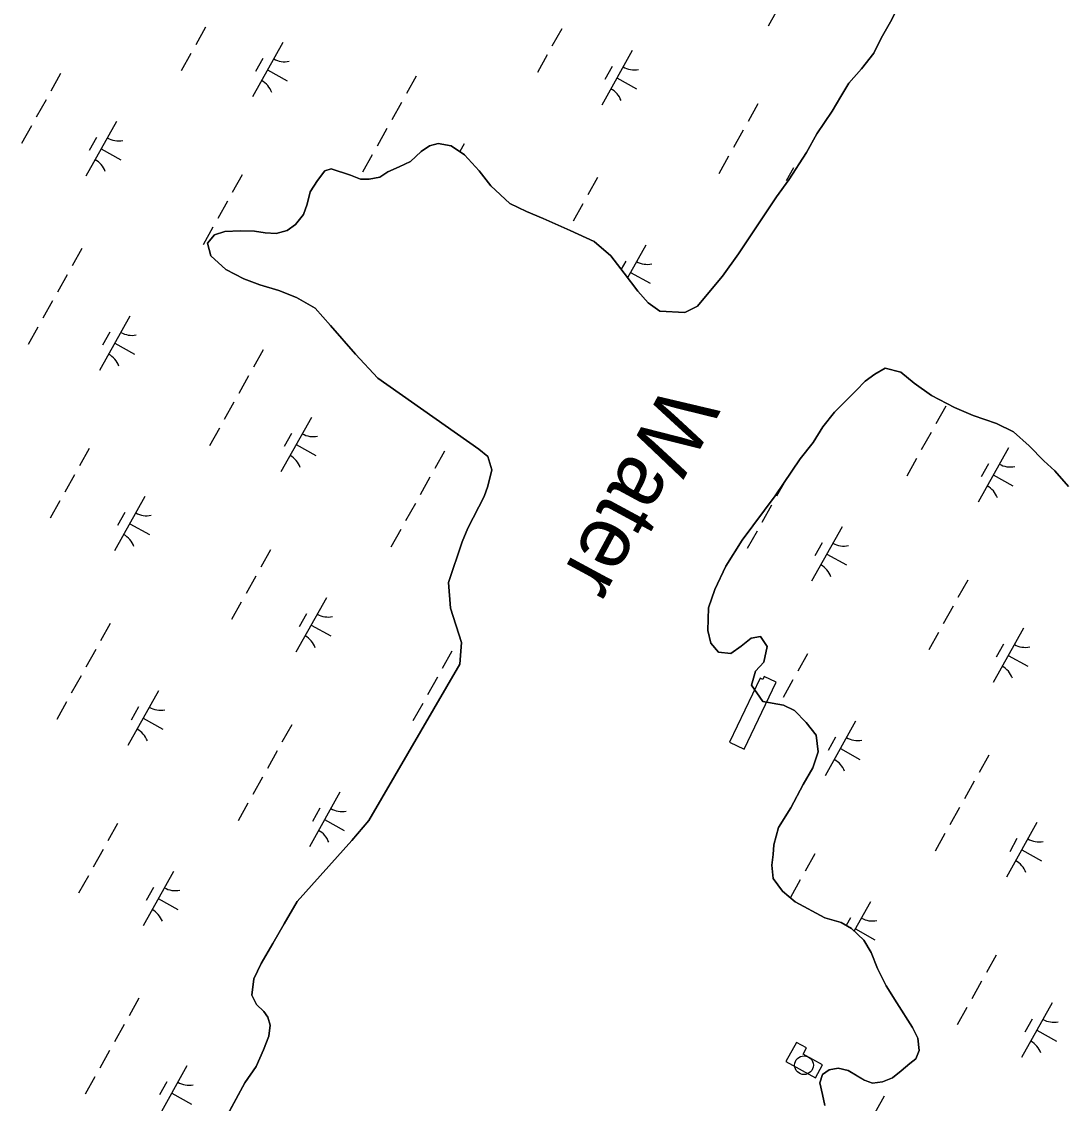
# Model space of a CAD drawing. Extents: x 3923531 to 3943530, y 207391 to 229799.
# Drawn here: x 3933394 to 3934228, y 219861 to 220728 of the extents above; entities that cross this region are included whole.
import ezdxf

# ---------------------------------------------------------------- set-up
doc = ezdxf.new("R2010")
doc.units = 0
for name, color, linetype in [('V-CHAN-DOCK', 7, 'Continuous'), ('V-DOMW-TANK', 7, 'Continuous'), ('V-RIVR-IDEN', 7, 'Continuous'), ('V-TOPO-SHOR', 7, 'Continuous'), ('V-WETL-SWMP', 7, 'Continuous')]:
    doc.layers.add(name, color=color, linetype=linetype)

msp = doc.modelspace()

# ---------------------------------------------------------------- linework, layer by layer
at = {"layer": 'V-CHAN-DOCK'}
for points in [[(3933984.89, 220201.83), (3933960.29, 220150.43), (3933971.99, 220144.83), (3933997.67, 220198.47), (3933988.17, 220203.02), (3933987.1, 220200.77)], [(3934034.88, 219892.13), (3934019.22, 219900.74), (3934021.97, 219905.73), (3934013.91, 219910.16), (3934005.47, 219894.8), (3934029.18, 219881.76)]]:
    msp.add_lwpolyline(points, close=True, dxfattribs=at)
at = {"layer": 'V-DOMW-TANK'}
msp.add_circle((3934019.97, 219891.86), 7.5, dxfattribs=at)
at = {"layer": 'V-TOPO-SHOR'}
for points in [[(3933542.45, 220550.23), (3933548.06, 220556.9), (3933556.4, 220559.39), (3933568.87, 220560.05), (3933580.14, 220559.73), (3933588.63, 220558.46), (3933597.53, 220557.77), (3933606.26, 220560.25), (3933612.83, 220564.93), (3933619.45, 220572.98), (3933622.3, 220581.46), (3933624.58, 220591.12), (3933630.41, 220600.36), (3933636.43, 220608.02), (3933641.59, 220609.74), (3933656.96, 220604.44), (3933664.85, 220601.39), (3933671.77, 220601.32), (3933680.49, 220603.01), (3933686.87, 220607.29), (3933696.01, 220611.16), (3933704.95, 220615.42), (3933713.54, 220623.44), (3933720.12, 220628.12), (3933727.06, 220629.83), (3933737.53, 220628.14), (3933748.14, 220620.9), (3933760.07, 220608.12), (3933769.25, 220596.15), (3933784.53, 220581.95), (3933797.92, 220575.48), (3933811.31, 220570), (3933832.78, 220560.28), (3933851.88, 220551.38), (3933865.41, 220539.96), (3933875.95, 220526.01), (3933886.88, 220511.65), (3933895.29, 220502.46), (3933904.52, 220495.64), (3933924.68, 220494.64), (3933934.83, 220499.68), (3933941.23, 220507.33), (3933954.66, 220523.81), (3933967.5, 220541.68), (3933998.05, 220587.26), (3934007.88, 220600.81), (3934021.96, 220622.82), (3934030.23, 220637.77), (3934042.48, 220655.84), (3934049.52, 220667.44), (3934055.77, 220678.26), (3934065.98, 220689.82), (3934076, 220702.38), (3934081.67, 220714.39), (3934089.12, 220727.37), (3934093.76, 220736.03)], [(3933550.1, 219836.96), (3933572.49, 219877.88), (3933581.52, 219890.84), (3933587.4, 219904.24), (3933591.67, 219915.07), (3933592.75, 219923.96), (3933590.83, 219930.32), (3933587.52, 219934.9), (3933581.64, 219940.5), (3933577.96, 219947.86), (3933579.68, 219960.9), (3933585.54, 219973.3), (3933594.81, 219989.43), (3933603.87, 220004.96), (3933614.15, 220023.05), (3933657.94, 220071.71), (3933671.64, 220087.9), (3933744.4, 220212.98), (3933745.85, 220230.32), (3933736.95, 220257.77), (3933735.38, 220278.46), (3933746.31, 220310.92), (3933750.78, 220321.95), (3933763.9, 220347.33), (3933766.96, 220355.61), (3933770.06, 220368.64), (3933766.81, 220379.36), (3933759.55, 220385.17), (3933678.88, 220441.89), (3933660.95, 220461.21), (3933640.88, 220484.12), (3933628.56, 220498.1), (3933613.81, 220506.56), (3933599.63, 220512.25), (3933584.44, 220516.76), (3933571.63, 220521.44), (3933557.07, 220529.11), (3933545.12, 220539.92), (3933542.45, 220550.23)], [(3933957.39, 220291.51), (3933970.46, 220312.34), (3933996.94, 220347.68), (3934016.83, 220377.35), (3934027.26, 220390.49), (3934035.1, 220403.07), (3934044.33, 220414.85), (3934061.72, 220432.27), (3934068.91, 220439.52), (3934076.69, 220445.17), (3934084.85, 220450.04), (3934097.48, 220446.94), (3934108.27, 220438.12), (3934122.01, 220428.09), (3934140.31, 220418.6), (3934155.48, 220412.11), (3934174.01, 220405.79), (3934187.79, 220398.92), (3934200.33, 220387.91), (3934212.08, 220375.72), (3934220.7, 220367.71), (3934231.65, 220355.34)], [(3934036.6, 219859.61), (3934034.71, 219868.53), (3934032.63, 219877.65), (3934034.68, 219884.36), (3934040.06, 219888.06), (3934047.2, 219889.37), (3934055.29, 219887.51), (3934068.27, 219879.86), (3934074.77, 219877.42), (3934082.69, 219878.52), (3934090.84, 219881.8), (3934097.62, 219887.46), (3934104.81, 219893.33), (3934109.59, 219897.04), (3934112.03, 219903.54), (3934111.15, 219913.44), (3934106.88, 219922.19), (3934094.23, 219941.9), (3934085.86, 219955.44), (3934078.88, 219969.36), (3934073.67, 219982.08), (3934067.84, 219992.03), (3934058.05, 220001.43), (3934049.59, 220006.27), (3934036.77, 220009.96), (3934012.77, 220022.67), (3934002.77, 220031.28), (3933995.16, 220041.45), (3933994.27, 220051.95), (3933995.16, 220060.64), (3933995.83, 220068.35), (3933999.53, 220082.16), (3934009.39, 220098.08), (3934019.28, 220116.58), (3934026.93, 220129.95), (3934031.22, 220142.77), (3934029.58, 220156.23), (3934021.77, 220166.4), (3934012.37, 220175.8), (3934003.52, 220180.04), (3933986.93, 220183.18), (3933977.96, 220196.14), (3933981.25, 220207.38), (3933987.85, 220214.63), (3933990.55, 220227.07), (3933985.09, 220235.23), (3933977.56, 220233.73), (3933969.78, 220227.28), (3933961.41, 220221.43), (3933951.53, 220222.72), (3933945.47, 220229.71), (3933943, 220240.02), (3933943.39, 220258.02), (3933948.69, 220272.8), (3933957.39, 220291.51)]]:
    msp.add_lwpolyline(points, dxfattribs=at)
at = {"layer": 'V-WETL-SWMP'}
for p, q in [((3934015.62, 220767.66), (3933991.23, 220724.01)), ((3934093.76, 220736.03), (3934089.12, 220727.37)), ((3934089.12, 220727.37), (3934081.66, 220714.39)), ((3933540.84, 220723.02), (3933533.04, 220709.05)), ((3933826.03, 220721.76), (3933818.23, 220707.8)), ((3933602.8, 220710.83), (3933578.41, 220667.18)), ((3934081.66, 220714.39), (3934076, 220702.38)), ((3933529.13, 220702.06), (3933521.33, 220688.09)), ((3933814.33, 220700.81), (3933806.53, 220686.84)), ((3933882.42, 220704.35), (3933858.03, 220660.7)), ((3934076, 220702.38), (3934065.98, 220689.82)), ((3933586.8, 220698), (3933580.94, 220687.53)), ((3933866.42, 220691.53), (3933860.56, 220681.05)), ((3933424.92, 220685.88), (3933417.12, 220671.91)), ((3933590.61, 220689), (3933606.32, 220680.22)), ((3933709.46, 220683.8), (3933701.66, 220669.83)), ((3933870.23, 220682.52), (3933885.94, 220673.75)), ((3934065.98, 220689.82), (3934055.77, 220678.26)), ((3934055.77, 220678.26), (3934049.52, 220667.44)), ((3933413.21, 220664.93), (3933405.41, 220650.96)), ((3934049.52, 220667.44), (3934042.48, 220655.84)), ((3933697.76, 220662.84), (3933689.95, 220648.87)), ((3933982.95, 220661.59), (3933975.15, 220647.62)), ((3934042.48, 220655.84), (3934030.22, 220637.77)), ((3933469.6, 220647.51), (3933445.21, 220603.86)), ((3933401.51, 220643.98), (3933393.71, 220630.01)), ((3933686.05, 220641.89), (3933678.25, 220627.92)), ((3933971.25, 220640.64), (3933963.44, 220626.67)), ((3933453.6, 220634.69), (3933447.74, 220624.21)), ((3933727.06, 220629.83), (3933720.12, 220628.12)), ((3933737.53, 220628.14), (3933727.06, 220629.83)), ((3933748.01, 220629.7), (3933744.49, 220623.39)), ((3934030.22, 220637.77), (3934021.96, 220622.82)), ((3933457.41, 220625.69), (3933473.12, 220616.91)), ((3933674.35, 220620.94), (3933666.54, 220606.97)), ((3933713.54, 220623.44), (3933704.95, 220615.42)), ((3933720.12, 220628.12), (3933713.54, 220623.44)), ((3933748.14, 220620.9), (3933737.53, 220628.14)), ((3934021.96, 220622.82), (3934007.88, 220600.81)), ((3933704.95, 220615.42), (3933696.01, 220611.16)), ((3933760.07, 220608.12), (3933748.14, 220620.9)), ((3933959.54, 220619.69), (3933951.74, 220605.72)), ((3933570.13, 220604.76), (3933562.33, 220590.79)), ((3933636.43, 220608.01), (3933630.41, 220600.36)), ((3933641.59, 220609.74), (3933636.43, 220608.01)), ((3933656.96, 220604.44), (3933641.59, 220609.74)), ((3933664.85, 220601.39), (3933656.96, 220604.44)), ((3933686.87, 220607.29), (3933680.49, 220603.01)), ((3933696.01, 220611.16), (3933686.87, 220607.29)), ((3933769.25, 220596.15), (3933760.07, 220608.12)), ((3934011.63, 220610.4), (3934005.78, 220599.93)), ((3933630.41, 220600.36), (3933624.58, 220591.12)), ((3933671.77, 220601.32), (3933664.85, 220601.39)), ((3933680.49, 220603.01), (3933671.77, 220601.32)), ((3933784.53, 220581.95), (3933769.25, 220596.15)), ((3933854.68, 220602.67), (3933846.87, 220588.7)), ((3934007.88, 220600.81), (3933998.05, 220587.26)), ((3933624.58, 220591.12), (3933622.3, 220581.45)), ((3933998.05, 220587.26), (3933967.51, 220541.68)), ((3933558.43, 220583.8), (3933550.63, 220569.84)), ((3933622.3, 220581.45), (3933619.45, 220572.98)), ((3933797.92, 220575.48), (3933784.53, 220581.95)), ((3933842.97, 220581.72), (3933835.17, 220567.75)), ((3933619.45, 220572.98), (3933612.83, 220564.93)), ((3933811.31, 220570), (3933797.92, 220575.48)), ((3933832.78, 220560.28), (3933811.31, 220570)), ((3933546.72, 220562.85), (3933538.92, 220548.88)), ((3933612.83, 220564.93), (3933606.26, 220560.25)), ((3933548.06, 220556.9), (3933542.45, 220550.23)), ((3933556.39, 220559.38), (3933548.06, 220556.9)), ((3933568.86, 220560.05), (3933556.39, 220559.38)), ((3933580.14, 220559.73), (3933568.86, 220560.05)), ((3933588.63, 220558.46), (3933580.14, 220559.73)), ((3933597.53, 220557.77), (3933588.63, 220558.46)), ((3933606.26, 220560.25), (3933597.53, 220557.77)), ((3933851.87, 220551.38), (3933832.78, 220560.28)), ((3933441.86, 220545.84), (3933434.05, 220531.87)), ((3933542.45, 220550.23), (3933545.11, 220539.92)), ((3933865.41, 220539.96), (3933851.87, 220551.38)), ((3933893.23, 220548.58), (3933878.64, 220522.47)), ((3933545.11, 220539.92), (3933557.07, 220529.11)), ((3933875.94, 220526.01), (3933865.41, 220539.96)), ((3933877.22, 220535.75), (3933873.55, 220529.18)), ((3933967.51, 220541.68), (3933954.66, 220523.81)), ((3933557.07, 220529.11), (3933571.63, 220521.44)), ((3933886.87, 220511.65), (3933875.94, 220526.01)), ((3933881.03, 220526.75), (3933896.75, 220517.97)), ((3933430.15, 220524.88), (3933422.35, 220510.91)), ((3933571.63, 220521.44), (3933584.44, 220516.76)), ((3933954.66, 220523.81), (3933941.23, 220507.33)), ((3933584.44, 220516.76), (3933599.63, 220512.25)), ((3933599.63, 220512.25), (3933613.81, 220506.56)), ((3933895.29, 220502.46), (3933886.87, 220511.65)), ((3933418.45, 220503.93), (3933410.64, 220489.96)), ((3933613.81, 220506.56), (3933628.56, 220498.1)), ((3933904.51, 220495.64), (3933895.29, 220502.46)), ((3933934.82, 220499.68), (3933924.68, 220494.64)), ((3933941.23, 220507.33), (3933934.82, 220499.68)), ((3933480.41, 220491.74), (3933456.02, 220448.09)), ((3933628.56, 220498.1), (3933640.88, 220484.12)), ((3933924.68, 220494.64), (3933904.51, 220495.64)), ((3933406.74, 220482.98), (3933398.94, 220469.01)), ((3933640.88, 220484.12), (3933660.95, 220461.21)), ((3933464.4, 220478.92), (3933458.55, 220468.44)), ((3933468.21, 220469.92), (3933483.93, 220461.14)), ((3933587.07, 220464.71), (3933579.27, 220450.74)), ((3933660.95, 220461.21), (3933678.88, 220441.89)), ((3934084.85, 220450.04), (3934076.69, 220445.17)), ((3934097.48, 220446.94), (3934084.85, 220450.04)), ((3933575.37, 220443.76), (3933567.56, 220429.79)), ((3933678.88, 220441.89), (3933759.55, 220385.17)), ((3934068.91, 220439.52), (3934061.72, 220432.27)), ((3934076.69, 220445.17), (3934068.91, 220439.52)), ((3934108.27, 220438.12), (3934097.48, 220446.94)), ((3934061.72, 220432.27), (3934044.33, 220414.85)), ((3934122.01, 220428.09), (3934108.27, 220438.12)), ((3933563.66, 220422.81), (3933555.86, 220408.84)), ((3934140.31, 220418.6), (3934122.01, 220428.09)), ((3934044.33, 220414.85), (3934035.1, 220403.07)), ((3934133.4, 220419.47), (3934125.6, 220405.5)), ((3934155.48, 220412.11), (3934140.31, 220418.6)), ((3933625.62, 220410.62), (3933601.23, 220366.97)), ((3934174.01, 220405.79), (3934155.48, 220412.11)), ((3934187.79, 220398.92), (3934174.01, 220405.79)), ((3933551.96, 220401.85), (3933544.15, 220387.89)), ((3933609.62, 220397.79), (3933603.77, 220387.32)), ((3934035.1, 220403.07), (3934027.26, 220390.49)), ((3934121.69, 220398.52), (3934113.89, 220384.55)), ((3934200.33, 220387.91), (3934187.79, 220398.92)), ((3933613.43, 220388.79), (3933629.14, 220380.01)), ((3934027.26, 220390.49), (3934016.83, 220377.34)), ((3934212.08, 220375.72), (3934200.33, 220387.91)), ((3933447.74, 220385.67), (3933439.94, 220371.7)), ((3933732.28, 220383.59), (3933724.48, 220369.62)), ((3933759.55, 220385.17), (3933766.81, 220379.35)), ((3933766.81, 220379.35), (3933770.06, 220368.64)), ((3934183.65, 220386.33), (3934159.27, 220342.68)), ((3934016.83, 220377.34), (3933996.94, 220347.68)), ((3934109.99, 220377.57), (3934102.19, 220363.6)), ((3934167.65, 220373.51), (3934161.8, 220363.03)), ((3934220.7, 220367.72), (3934212.08, 220375.72)), ((3933436.04, 220364.72), (3933428.23, 220350.75)), ((3933720.58, 220362.63), (3933712.78, 220348.67)), ((3933770.06, 220368.64), (3933766.96, 220355.61)), ((3934171.46, 220364.51), (3934187.18, 220355.73)), ((3934231.65, 220355.34), (3934220.7, 220367.72)), ((3933766.96, 220355.61), (3933763.9, 220347.34)), ((3934003.99, 220358.19), (3933997.97, 220347.42)), ((3933424.33, 220343.77), (3933416.53, 220329.8)), ((3933492.42, 220347.31), (3933468.03, 220303.65)), ((3933763.9, 220347.34), (3933750.78, 220321.95)), ((3933996.94, 220347.68), (3933970.46, 220312.34)), ((3933708.87, 220341.68), (3933701.07, 220327.71)), ((3933994.07, 220340.43), (3933986.27, 220326.46)), ((3933476.42, 220334.48), (3933470.56, 220324)), ((3933480.23, 220325.48), (3933495.94, 220316.7)), ((3933697.17, 220320.73), (3933689.37, 220306.76)), ((3933750.78, 220321.95), (3933746.31, 220310.92)), ((3933982.37, 220319.48), (3933974.56, 220305.51)), ((3934050.45, 220323.02), (3934026.07, 220279.37)), ((3933746.31, 220310.92), (3933735.38, 220278.46)), ((3933970.46, 220312.34), (3933957.39, 220291.51)), ((3934034.45, 220310.19), (3934028.6, 220299.72)), ((3933592.95, 220304.55), (3933585.15, 220290.58)), ((3934038.26, 220301.19), (3934053.97, 220292.41)), ((3933581.25, 220283.59), (3933573.45, 220269.63)), ((3933957.39, 220291.51), (3933948.69, 220272.8)), ((3933735.38, 220278.46), (3933736.95, 220257.77)), ((3934150.99, 220280.26), (3934143.19, 220266.29)), ((3933637.63, 220266.18), (3933613.25, 220222.53)), ((3933948.69, 220272.8), (3933943.39, 220258.02)), ((3933569.54, 220262.64), (3933561.74, 220248.67)), ((3933736.95, 220257.77), (3933745.85, 220230.32)), ((3933943.39, 220258.02), (3933943.01, 220240.02)), ((3934139.28, 220259.31), (3934131.48, 220245.34)), ((3933621.63, 220253.36), (3933615.78, 220242.88)), ((3933464.68, 220245.63), (3933456.87, 220231.66)), ((3933625.44, 220244.36), (3933641.15, 220235.58)), ((3933943.01, 220240.02), (3933945.47, 220229.71)), ((3934195.67, 220241.89), (3934171.28, 220198.24)), ((3933969.78, 220227.28), (3933977.56, 220233.73)), ((3933977.56, 220233.73), (3933985.09, 220235.23)), ((3933985.09, 220235.23), (3933990.55, 220227.07)), ((3934127.58, 220238.36), (3934119.78, 220224.39)), ((3933452.97, 220224.67), (3933445.17, 220210.71)), ((3933738.17, 220223.42), (3933730.36, 220209.45)), ((3933745.85, 220230.32), (3933744.4, 220212.98)), ((3933945.47, 220229.71), (3933951.53, 220222.72)), ((3933951.53, 220222.72), (3933961.41, 220221.43)), ((3933961.41, 220221.43), (3933969.78, 220227.28)), ((3933990.55, 220227.07), (3933987.85, 220214.63)), ((3934179.66, 220229.07), (3934173.81, 220218.59)), ((3933987.85, 220214.63), (3933981.25, 220207.38)), ((3934022.71, 220221.34), (3934014.91, 220207.37)), ((3934183.47, 220220.07), (3934199.19, 220211.29)), ((3933744.4, 220212.98), (3933671.64, 220087.9)), ((3933981.25, 220207.38), (3933977.96, 220196.14)), ((3933441.27, 220203.72), (3933433.46, 220189.75)), ((3933726.46, 220202.47), (3933718.66, 220188.5)), ((3934011.01, 220200.39), (3934003.2, 220186.42)), ((3933503.23, 220191.53), (3933478.84, 220147.88)), ((3933977.96, 220196.14), (3933986.93, 220183.18)), ((3933429.56, 220182.77), (3933421.76, 220168.8)), ((3933714.76, 220181.52), (3933706.95, 220167.55)), ((3933986.93, 220183.18), (3934003.52, 220180.04)), ((3934003.52, 220180.04), (3934012.37, 220175.8)), ((3933487.23, 220178.71), (3933481.37, 220168.23)), ((3934012.37, 220175.8), (3934021.77, 220166.4)), ((3933491.03, 220169.71), (3933506.75, 220160.93)), ((3933609.89, 220164.5), (3933602.09, 220150.53)), ((3934021.77, 220166.4), (3934029.58, 220156.23)), ((3934061.26, 220167.25), (3934036.88, 220123.6)), ((3934029.58, 220156.23), (3934031.22, 220142.76)), ((3934045.26, 220154.42), (3934039.41, 220143.95)), ((3934049.07, 220145.42), (3934064.78, 220136.64)), ((3933598.19, 220143.55), (3933590.38, 220129.58)), ((3934031.22, 220142.76), (3934026.93, 220129.95)), ((3934167.93, 220140.21), (3934160.12, 220126.25)), ((3934026.93, 220129.95), (3934019.28, 220116.58)), ((3933586.48, 220122.6), (3933578.68, 220108.63)), ((3934156.22, 220119.26), (3934148.42, 220105.29)), ((3933648.44, 220110.41), (3933624.06, 220066.76)), ((3934019.28, 220116.58), (3934009.39, 220098.08)), ((3933574.78, 220101.65), (3933566.97, 220087.68)), ((3933632.44, 220097.59), (3933626.59, 220087.11)), ((3934009.39, 220098.08), (3933999.53, 220082.16)), ((3934144.52, 220098.31), (3934136.71, 220084.34)), ((3933470.56, 220085.46), (3933462.76, 220071.49)), ((3933636.25, 220088.58), (3933651.96, 220079.81)), ((3933671.64, 220087.9), (3933657.94, 220071.7)), ((3934206.48, 220086.12), (3934182.09, 220042.47)), ((3933999.53, 220082.16), (3933995.83, 220068.35)), ((3934132.81, 220077.36), (3934125.01, 220063.39)), ((3933657.94, 220071.7), (3933614.15, 220023.05)), ((3933995.83, 220068.35), (3933995.16, 220060.64)), ((3934190.47, 220073.3), (3934184.62, 220062.82)), ((3933458.86, 220064.51), (3933451.05, 220050.54)), ((3933995.16, 220060.64), (3933994.28, 220051.95)), ((3934028.6, 220061.17), (3934020.79, 220047.21)), ((3934194.28, 220064.3), (3934210, 220055.52)), ((3933994.28, 220051.95), (3933995.16, 220041.45)), ((3933447.15, 220043.56), (3933439.35, 220029.59)), ((3933515.24, 220047.1), (3933490.86, 220003.45)), ((3933995.16, 220041.45), (3934002.77, 220031.28)), ((3933499.24, 220034.27), (3933493.39, 220023.8)), ((3934016.89, 220040.22), (3934009.09, 220026.25)), ((3933503.05, 220025.27), (3933518.76, 220016.49)), ((3934002.77, 220031.28), (3934012.77, 220022.67)), ((3933614.15, 220023.05), (3933603.87, 220004.96)), ((3934012.77, 220022.67), (3934036.77, 220009.96)), ((3934073.27, 220022.81), (3934060.19, 219999.38)), ((3934036.77, 220009.96), (3934049.59, 220006.27)), ((3934049.59, 220006.27), (3934058.05, 220001.43)), ((3934057.27, 220009.98), (3934053.84, 220003.84)), ((3933603.87, 220004.96), (3933594.81, 219989.43)), ((3934058.05, 220001.43), (3934067.84, 219992.03)), ((3934061.08, 220000.98), (3934076.8, 219992.2)), ((3933594.81, 219989.43), (3933585.54, 219973.3)), ((3934067.84, 219992.03), (3934073.67, 219982.08)), ((3934073.67, 219982.08), (3934078.88, 219969.36)), ((3934173.81, 219980.05), (3934166.01, 219966.08)), ((3933585.54, 219973.3), (3933579.68, 219960.9)), ((3934078.88, 219969.36), (3934085.86, 219955.44)), ((3933579.68, 219960.9), (3933577.96, 219947.86)), ((3934085.86, 219955.44), (3934094.23, 219941.9)), ((3934162.1, 219959.1), (3934154.3, 219945.13)), ((3933487.5, 219945.42), (3933479.7, 219931.45)), ((3933577.96, 219947.86), (3933581.64, 219940.5)), ((3933581.64, 219940.5), (3933587.52, 219934.9)), ((3934094.23, 219941.9), (3934106.88, 219922.19)), ((3934150.4, 219938.15), (3934142.6, 219924.18)), ((3934218.49, 219941.68), (3934194.1, 219898.03)), ((3933587.52, 219934.9), (3933590.83, 219930.31)), ((3933590.83, 219930.31), (3933592.75, 219923.96)), ((3934202.49, 219928.86), (3934196.63, 219918.38)), ((3933475.79, 219924.47), (3933467.99, 219910.5)), ((3933592.75, 219923.96), (3933591.67, 219915.07)), ((3934106.88, 219922.19), (3934111.15, 219913.44)), ((3934206.3, 219919.86), (3934222.01, 219911.08)), ((3933591.67, 219915.07), (3933587.4, 219904.24)), ((3934111.15, 219913.44), (3934112.03, 219903.54)), ((3933464.09, 219903.51), (3933456.29, 219889.55)), ((3933587.4, 219904.24), (3933581.52, 219890.84)), ((3934112.03, 219903.54), (3934109.59, 219897.04)), ((3934109.59, 219897.04), (3934104.8, 219893.33)), ((3933526.05, 219891.33), (3933501.66, 219847.67)), ((3933581.52, 219890.84), (3933572.49, 219877.88)), ((3934040.06, 219888.06), (3934034.68, 219884.36)), ((3934047.19, 219889.37), (3934040.06, 219888.06)), ((3934055.29, 219887.51), (3934047.19, 219889.37)), ((3934068.26, 219879.86), (3934055.29, 219887.51)), ((3934097.62, 219887.47), (3934090.84, 219881.8)), ((3934104.8, 219893.33), (3934097.62, 219887.47)), ((3933452.38, 219882.56), (3933444.58, 219868.59)), ((3933510.05, 219878.5), (3933504.19, 219868.02)), ((3933572.49, 219877.88), (3933550.1, 219836.96)), ((3934034.68, 219884.36), (3934032.63, 219877.65)), ((3934032.63, 219877.65), (3934034.71, 219868.53)), ((3934074.77, 219877.41), (3934068.26, 219879.86)), ((3934082.69, 219878.52), (3934074.77, 219877.41)), ((3934090.84, 219881.8), (3934082.69, 219878.52)), ((3933513.86, 219869.5), (3933529.57, 219860.72)), ((3934034.71, 219868.53), (3934036.6, 219859.61)), ((3934084.08, 219867.04), (3934059.7, 219823.39))]:
    msp.add_line(p, q, dxfattribs=at)
for centre, start, end in [((3933604.28, 220713), 240.03808, 281.58174), ((3933883.9, 220706.52), 240.03808, 281.58174), ((3933577.34, 220664.77), 20.03808, 61.58174), ((3933856.96, 220658.3), 20.03808, 61.58174), ((3933471.08, 220649.69), 240.03808, 281.58174), ((3933444.14, 220601.46), 20.03808, 61.58174), ((3933894.71, 220550.75), 240.03808, 281.58174), ((3933481.89, 220493.92), 240.03808, 281.58174), ((3933454.95, 220445.69), 20.03808, 61.58174), ((3933627.11, 220412.79), 240.03808, 281.58174), ((3933600.16, 220364.56), 20.03808, 61.58174), ((3934185.14, 220388.5), 240.03808, 281.58174), ((3934158.2, 220340.28), 20.03808, 61.58174), ((3933493.9, 220349.48), 240.03808, 281.58174), ((3933466.96, 220301.25), 20.03808, 61.58174), ((3934051.94, 220325.19), 240.03808, 281.58174), ((3934025, 220276.96), 20.03808, 61.58174), ((3933639.12, 220268.35), 240.03808, 281.58174), ((3933612.18, 220220.13), 20.03808, 61.58174), ((3934197.15, 220244.07), 240.03808, 281.58174), ((3934170.21, 220195.84), 20.03808, 61.58174), ((3933504.71, 220193.71), 240.03808, 281.58174), ((3933477.77, 220145.48), 20.03808, 61.58174), ((3934062.75, 220169.42), 240.03808, 281.58174), ((3934035.8, 220121.19), 20.03808, 61.58174), ((3933649.93, 220112.58), 240.03808, 281.58174), ((3933622.98, 220064.36), 20.03808, 61.58174), ((3934207.96, 220088.29), 240.03808, 281.58174), ((3934181.02, 220040.07), 20.03808, 61.58174), ((3933516.73, 220049.27), 240.03808, 281.58174), ((3933489.78, 220001.04), 20.03808, 61.58174), ((3934074.76, 220024.98), 240.03808, 281.58174), ((3934219.97, 219943.86), 240.03808, 281.58174), ((3934193.03, 219895.63), 20.03808, 61.58174), ((3933527.53, 219893.5), 240.03808, 281.58174)]:
    msp.add_arc(centre, 17.62, start, end, dxfattribs=at)

# ---------------------------------------------------------------- texts
at = {"layer": 'V-RIVR-IDEN'}
msp.add_text('Water', height=50, rotation=241.58945, dxfattribs=at).set_placement((3933909.46, 220439.69))

doc.saveas('drawing.dxf')
